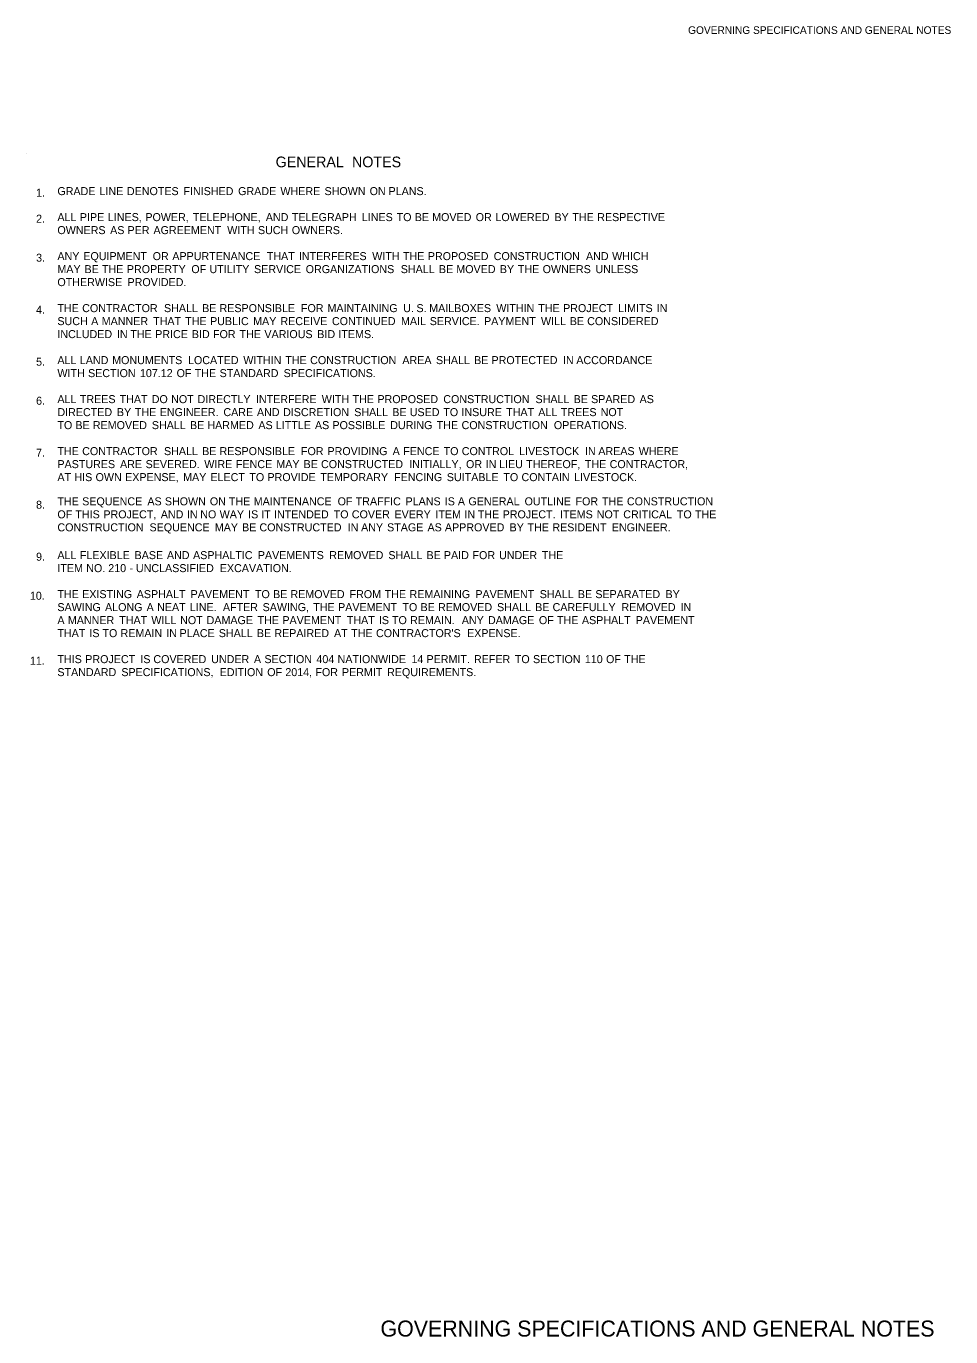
# Model space of a CAD drawing. Extents: x -2857 to 1648, y -1031 to 968.
# Drawn here: x 261 to 1648, y -1031 to 935 of the extents above; entities that cross this region are included whole.
import ezdxf

# ---------------------------------------------------------------- set-up
doc = ezdxf.new("R2010")
doc.units = 0
for name, color, linetype in [('Default', 7, 'Continuous'), ('R_Annotation', 7, 'Continuous'), ('R_Border', 7, 'Continuous')]:
    doc.layers.add(name, color=color, linetype=linetype)

msp = doc.modelspace()

# ---------------------------------------------------------------- linework, layer by layer
at = {"layer": 'Default'}
msp.add_line((261, 744.8), (261, 744.8), dxfattribs=at)

# ---------------------------------------------------------------- texts
for s, height, p in [('GENERAL', 16, (635.1, 723.6)), (' NOTES', 16, (743.7, 723.6)), ('1.', 12, (275.8, 679.4)), ('GRADE', 12, (307.8, 681.8)), (' LINE', 12, (366.5, 681.8)), (' DENOTES', 12, (407.6, 681.8)), (' FINISHED', 12, (492.4, 681.8)), (' GRADE', 12, (574.4, 681.8)), (' WHERE', 12, (637.8, 681.8)), (' SHOWN', 12, (704, 681.8)), (' ON', 12, (771.6, 681.8)), (' PLANS.', 12, (800, 681.8)), ('2.', 12, (275.8, 640.4)), ('ALL', 12, (307.8, 642.8)), (' PIPE', 12, (337, 642.8)), (' LINES,', 12, (379, 642.8)), (' POWER,', 12, (435.3, 642.8)), (' TELEPHONE,', 12, (506.5, 642.8)), (' AND', 12, (615.9, 642.8)), (' TELEGRAPH', 12, (655, 642.8)), (' LINES', 12, (759.9, 642.8)), (' TO', 12, (812.1, 642.8)), (' BE', 12, (839.3, 642.8)), (' MOVED', 12, (865.4, 642.8)), (' OR', 12, (930.7, 642.8)), (' LOWERED', 12, (960.3, 642.8)), (' BY', 12, (1048.8, 642.8)), (' THE', 12, (1075.7, 642.8)), (' RESPECTIVE', 12, (1113, 642.8)), ('OWNERS', 12, (307.8, 623.3)), (' AS', 12, (382.4, 623.3)), (' PER', 12, (408.5, 623.3)), (' AGREEMENT', 12, (447.4, 623.3)), (' WITH', 12, (558, 623.3)), (' SUCH', 12, (604.1, 623.3)), (' OWNERS.', 12, (654.9, 623.3)), ('3.', 12, (275.8, 581.9)), ('ANY', 12, (307.8, 584.3)), (' EQUIPMENT', 12, (342.2, 584.3)), (' OR', 12, (446.2, 584.3)), (' APPURTENANCE', 12, (475.7, 584.3)), (' THAT', 12, (617.4, 584.3)), (' INTERFERES', 12, (665.5, 584.3)), (' WITH', 12, (775.5, 584.3)), (' THE', 12, (821.6, 584.3)), (' PROPOSED', 12, (858.9, 584.3)), (' CONSTRUCTION', 12, (957.7, 584.3)), (' AND', 12, (1096.1, 584.3)), (' WHICH', 12, (1135.3, 584.3)), ('MAY', 12, (307.8, 564.8)), (' BE', 12, (344, 564.8)), (' THE', 12, (370.2, 564.8)), (' PROPERTY', 12, (407.5, 564.8)), (' OF', 12, (504.2, 564.8)), (' UTILITY', 12, (531.4, 564.8)), (' SERVICE', 12, (598.3, 564.8)), (' ORGANIZATIONS', 12, (675.7, 564.8)), (' SHALL', 12, (818.3, 564.8)), (' BE', 12, (875.5, 564.8)), (' MOVED', 12, (901.6, 564.8)), (' BY', 12, (966.9, 564.8)), (' THE', 12, (993.8, 564.8)), (' OWNERS', 12, (1031.1, 564.8)), (' UNLESS', 12, (1110.3, 564.8)), ('OTHERWISE', 12, (307.8, 545.3)), (' PROVIDED.', 12, (408.5, 545.3)), ('4.', 12, (275.8, 503.9)), ('THE', 12, (307.8, 506.3)), (' CONTRACTOR', 12, (340.5, 506.3)), (' SHALL', 12, (463.2, 506.3)), (' BE', 12, (520.4, 506.3)), (' RESPONSIBLE', 12, (546.5, 506.3)), (' FOR', 12, (668.6, 506.3)), (' MAINTAINING', 12, (708.4, 506.3)), (' U.', 12, (822, 506.3)), (' S.', 12, (841.9, 506.3)), (' MAILBOXES', 12, (861, 506.3)), (' WITHIN', 12, (961.6, 506.3)), (' THE', 12, (1024.5, 506.3)), (' PROJECT', 12, (1061.8, 506.3)), (' LIMITS', 12, (1144.4, 506.3)), (' IN', 12, (1202.2, 506.3)), ('SUCH', 12, (307.8, 486.8)), (' A', 12, (354, 486.8)), (' MANNER', 12, (369.8, 486.8)), (' THAT', 12, (446.9, 486.8)), (' THE', 12, (495, 486.8)), (' PUBLIC', 12, (532.3, 486.8)), (' MAY', 12, (596.9, 486.8)), (' RECEIVE', 12, (637.8, 486.8)), (' CONTINUED', 12, (715.1, 486.8)), (' MAIL', 12, (818.6, 486.8)), (' SERVICE.', 12, (861.8, 486.8)), (' PAYMENT', 12, (943.2, 486.8)), (' WILL', 12, (1028.6, 486.8)), (' BE', 12, (1071.8, 486.8)), (' CONSIDERED', 12, (1097.9, 486.8)), ('INCLUDED', 12, (307.8, 467.3)), (' IN', 12, (392.6, 467.3)), (' THE', 12, (412.7, 467.3)), (' PRICE', 12, (450, 467.3)), (' BID', 12, (505, 467.3)), (' FOR', 12, (536.7, 467.3)), (' THE', 12, (576.5, 467.3)), (' VARIOUS', 12, (613.8, 467.3)), (' BID', 12, (693.1, 467.3)), (' ITEMS.', 12, (724.8, 467.3)), ('5.', 12, (275.8, 425.9)), ('ALL', 12, (307.8, 428.3)), (' LAND', 12, (337, 428.3)), (' MONUMENTS', 12, (385.5, 428.3)), (' LOCATED', 12, (499.2, 428.3)), (' WITHIN', 12, (582.2, 428.3)), (' THE', 12, (645.1, 428.3)), (' CONSTRUCTION', 12, (682.4, 428.3)), (' AREA', 12, (820.7, 428.3)), (' SHALL', 12, (871.1, 428.3)), (' BE', 12, (928.3, 428.3)), (' PROTECTED', 12, (954.4, 428.3)), (' IN', 12, (1061.6, 428.3)), (' ACCORDANCE', 12, (1081.6, 428.3)), ('WITH', 12, (307.8, 408.8)), (' SECTION', 12, (349.3, 408.8)), (' 107.12', 12, (427.1, 408.8)), (' OF', 12, (482.1, 408.8)), (' THE', 12, (509.3, 408.8)), (' STANDARD', 12, (546.6, 408.8)), (' SPECIFICATIONS.', 12, (642.6, 408.8)), ('6.', 12, (275.8, 367.4)), ('ALL', 12, (307.8, 369.8)), (' TREES', 12, (337, 369.8)), (' THAT', 12, (396.7, 369.8)), (' DO', 12, (444.8, 369.8)), (' NOT', 12, (473.9, 369.8)), (' DIRECTLY', 12, (513.6, 369.8)), (' INTERFERE', 12, (601.1, 369.8)), (' WITH', 12, (699.8, 369.8)), (' THE', 12, (746, 369.8)), (' PROPOSED', 12, (783.3, 369.8)), (' CONSTRUCTION', 12, (882.1, 369.8)), (' SHALL', 12, (1020.4, 369.8)), (' BE', 12, (1077.6, 369.8)), (' SPARED', 12, (1103.8, 369.8)), (' AS', 12, (1176.5, 369.8)), ('DIRECTED', 12, (307.8, 350.3)), (' BY', 12, (392.6, 350.3)), (' THE', 12, (419.5, 350.3)), (' ENGINEER.', 12, (456.8, 350.3)), (' CARE', 12, (552.3, 350.3)), (' AND', 12, (602.6, 350.3)), (' DISCRETION', 12, (641.8, 350.3)), (' SHALL', 12, (748.5, 350.3)), (' BE', 12, (805.6, 350.3)), (' USED', 12, (831.8, 350.3)), (' TO', 12, (882.1, 350.3)), (' INSURE', 12, (909.3, 350.3)), (' THAT', 12, (976.4, 350.3)), (' ALL', 12, (1024.5, 350.3)), (' TREES', 12, (1058.4, 350.3)), (' NOT', 12, (1118.1, 350.3)), ('TO', 12, (307.8, 330.8)), (' BE', 12, (330.3, 330.8)), (' REMOVED', 12, (356.5, 330.8)), (' SHALL', 12, (445, 330.8)), (' BE', 12, (502.2, 330.8)), (' HARMED', 12, (528.3, 330.8)), (' AS', 12, (604.8, 330.8)), (' LITTLE', 12, (630.9, 330.8)), (' AS', 12, (689.6, 330.8)), (' POSSIBLE', 12, (715.8, 330.8)), (' DURING', 12, (802.5, 330.8)), (' THE', 12, (872.2, 330.8)), (' CONSTRUCTION', 12, (909.5, 330.8)), (' OPERATIONS.', 12, (1047.9, 330.8)), ('7.', 12, (275.8, 289.4)), ('THE', 12, (307.8, 291.8)), (' CONTRACTOR', 12, (340.5, 291.8)), (' SHALL', 12, (463.2, 291.8)), (' BE', 12, (520.4, 291.8)), (' RESPONSIBLE', 12, (546.5, 291.8)), (' FOR', 12, (668.6, 291.8)), (' PROVIDING', 12, (708.4, 291.8)), (' A', 12, (806.1, 291.8)), (' FENCE', 12, (822, 291.8)), (' TO', 12, (882.6, 291.8)), (' CONTROL', 12, (909.8, 291.8)), (' LIVESTOCK', 12, (995.8, 291.8)), (' IN', 12, (1094.6, 291.8)), (' AREAS', 12, (1114.6, 291.8)), (' WHERE', 12, (1175.2, 291.8)), ('PASTURES', 12, (307.8, 272.3)), (' ARE', 12, (397.3, 272.3)), (' SEVERED.', 12, (435.6, 272.3)), (' WIRE', 12, (523.6, 272.3)), (' FENCE', 12, (571.1, 272.3)), (' MAY', 12, (631.7, 272.3)), (' BE', 12, (672.6, 272.3)), (' CONSTRUCTED', 12, (698.7, 272.3)), (' INITIALLY,', 12, (831, 272.3)), (' OR', 12, (916.2, 272.3)), (' IN', 12, (945.7, 272.3)), (' LIEU', 12, (965.8, 272.3)), (' THEREOF,', 12, (1006.4, 272.3)), (' THE', 12, (1094.3, 272.3)), (' CONTRACTOR,', 12, (1131.6, 272.3)), ('AT', 12, (307.8, 252.8)), (' HIS', 12, (328.9, 252.8)), (' OWN', 12, (360.6, 252.8)), (' EXPENSE,', 12, (404.9, 252.8)), (' MAY', 12, (491.9, 252.8)), (' ELECT', 12, (532.8, 252.8)), (' TO', 12, (591.2, 252.8)), (' PROVIDE', 12, (618.4, 252.8)), (' TEMPORARY', 12, (697.6, 252.8)), (' FENCING', 12, (808.3, 252.8)), (' SUITABLE', 12, (887.4, 252.8)), (' TO', 12, (972.2, 252.8)), (' CONTAIN', 12, (999.4, 252.8)), (' LIVESTOCK.', 12, (1078.2, 252.8)), ('8.', 12, (275.8, 211.4)), ('THE', 12, (307.8, 216.5)), (' SEQUENCE', 12, (340.5, 216.5)), (' AS', 12, (438.3, 216.5)), (' SHOWN', 12, (464.5, 216.5)), (' ON', 12, (532, 216.5)), (' THE', 12, (560.5, 216.5)), (' MAINTENANCE', 12, (597.8, 216.5)), (' OF', 12, (723.6, 216.5)), (' TRAFFIC', 12, (750.7, 216.5)), (' PLANS', 12, (825.5, 216.5)), (' IS', 12, (884.3, 216.5)), (' A', 12, (903.9, 216.5)), (' GENERAL', 12, (919.8, 216.5)), (' OUTLINE', 12, (1004, 216.5)), (' FOR', 12, (1080.4, 216.5)), (' THE', 12, (1120.2, 216.5)), (' CONSTRUCTION', 12, (1157.5, 216.5)), ('OF', 12, (307.8, 197)), (' THIS', 12, (330.3, 197)), (' PROJECT,', 12, (372.3, 197)), (' AND', 12, (458.4, 197)), (' IN', 12, (497.6, 197)), (' NO', 12, (517.6, 197)), (' WAY', 12, (546.7, 197)), (' IS', 12, (589.4, 197)), (' IT', 12, (609, 197)), (' INTENDED', 12, (628.2, 197)), (' TO', 12, (717.7, 197)), (' COVER', 12, (744.9, 197)), (' EVERY', 12, (808.9, 197)), (' ITEM', 12, (870.3, 197)), (' IN', 12, (913.8, 197)), (' THE', 12, (933.8, 197)), (' PROJECT.', 12, (971.1, 197)), (' ITEMS', 12, (1057.2, 197)), (' NOT', 12, (1112.2, 197)), (' CRITICAL', 12, (1152, 197)), (' TO', 12, (1232.4, 197)), (' THE', 12, (1259.6, 197)), ('CONSTRUCTION', 12, (307.8, 177.5)), (' SEQUENCE', 12, (441.5, 177.5)), (' MAY', 12, (539.4, 177.5)), (' BE', 12, (580.3, 177.5)), (' CONSTRUCTED', 12, (606.4, 177.5)), (' IN', 12, (738.7, 177.5)), (' ANY', 12, (758.8, 177.5)), (' STAGE', 12, (797.8, 177.5)), (' AS', 12, (858.4, 177.5)), (' APPROVED', 12, (884.5, 177.5)), (' BY', 12, (981.5, 177.5)), (' THE', 12, (1008.4, 177.5)), (' RESIDENT', 12, (1045.7, 177.5)), (' ENGINEER.', 12, (1134.8, 177.5)), ('9.', 12, (275.8, 133.4)), ('ALL', 12, (307.8, 135.8)), (' FLEXIBLE', 12, (337, 135.8)), (' BASE', 12, (419.1, 135.8)), (' AND', 12, (467.6, 135.8)), (' ASPHALTIC', 12, (506.8, 135.8)), (' PAVEMENTS', 12, (603.9, 135.8)), (' REMOVED', 12, (711.1, 135.8)), (' SHALL', 12, (799.7, 135.8)), (' BE', 12, (856.9, 135.8)), (' PAID', 12, (883, 135.8)), (' FOR', 12, (925.9, 135.8)), (' UNDER', 12, (965.7, 135.8)), (' THE', 12, (1029.8, 135.8)), ('ITEM', 12, (307.8, 116.3)), (' NO.', 12, (346.6, 116.3)), (' 210', 12, (379.6, 116.3)), (' -', 12, (411.4, 116.3)), (' UNCLASSIFIED', 12, (421.1, 116.3)), (' EXCAVATION.', 12, (546.9, 116.3)), ('10.', 12, (266.5, 74.9)), ('THE', 12, (307.8, 77.3)), (' EXISTING', 12, (340.5, 77.3)), (' ASPHALT', 12, (422.3, 77.3)), (' PAVEMENT', 12, (503.1, 77.3)), (' TO', 12, (599.6, 77.3)), (' BE', 12, (626.8, 77.3)), (' REMOVED', 12, (652.9, 77.3)), (' FROM', 12, (741.5, 77.3)), (' THE', 12, (794.2, 77.3)), (' REMAINING', 12, (831.5, 77.3)), (' PAVEMENT', 12, (930.2, 77.3)), (' SHALL', 12, (1026.7, 77.3)), (' BE', 12, (1083.9, 77.3)), (' SEPARATED', 12, (1110.1, 77.3)), (' BY', 12, (1215.4, 77.3)), ('SAWING', 12, (307.8, 57.8)), (' ALONG', 12, (374.8, 57.8)), (' A', 12, (437.1, 57.8)), (' NEAT', 12, (452.9, 57.8)), (' LINE.', 12, (502, 57.8)), ('  AFTER', 12, (547.1, 57.8)), (' SAWING,', 12, (611.1, 57.8)), (' THE', 12, (687, 57.8)), (' PAVEMENT', 12, (724.3, 57.8)), (' TO', 12, (820.8, 57.8)), (' BE', 12, (848, 57.8)), (' REMOVED', 12, (874.2, 57.8)), (' SHALL', 12, (962.7, 57.8)), (' BE', 12, (1019.9, 57.8)), (' CAREFULLY', 12, (1046, 57.8)), (' REMOVED', 12, (1149.3, 57.8)), (' IN', 12, (1237.9, 57.8)), ('A', 12, (307.8, 38.3)), (' MANNER', 12, (319, 38.3)), (' THAT', 12, (396.1, 38.3)), (' WILL', 12, (444.2, 38.3)), (' NOT', 12, (487.4, 38.3)), (' DAMAGE', 12, (527.1, 38.3)), (' THE', 12, (603.5, 38.3)), (' PAVEMENT', 12, (640.8, 38.3)), (' THAT', 12, (737.4, 38.3)), (' IS', 12, (785.5, 38.3)), (' TO', 12, (805.1, 38.3)), (' REMAIN.', 12, (832.3, 38.3)), ('  ANY', 12, (905.4, 38.3)), (' DAMAGE', 12, (949.1, 38.3)), (' OF', 12, (1025.5, 38.3)), (' THE', 12, (1052.7, 38.3)), (' ASPHALT', 12, (1090, 38.3)), (' PAVEMENT', 12, (1170.7, 38.3)), ('THAT', 12, (307.8, 18.8)), (' IS', 12, (351.3, 18.8)), (' TO', 12, (370.9, 18.8)), (' REMAIN', 12, (398.1, 18.8)), (' IN', 12, (466.6, 18.8)), (' PLACE', 12, (486.6, 18.8)), (' SHALL', 12, (545.4, 18.8)), (' BE', 12, (602.5, 18.8)), (' REPAIRED', 12, (628.7, 18.8)), (' AT', 12, (718.2, 18.8)), (' THE', 12, (743.9, 18.8)), (" CONTRACTOR'S", 12, (781.2, 18.8)), (' EXPENSE.', 12, (917.7, 18.8)), ('11.', 12, (266.5, -22.6)), ('THIS', 12, (307.8, -20.2)), (' PROJECT', 12, (345.1, -20.2)), (' IS', 12, (427.7, -20.2)), (' COVERED', 12, (447.3, -20.2)), (' UNDER', 12, (534, -20.2)), (' A', 12, (598.1, -20.2)), (' SECTION', 12, (613.9, -20.2)), (' 404', 12, (691.8, -20.2)), (' NATIONWIDE', 12, (723.6, -20.2)), (' 14', 12, (834.4, -20.2)), (' PERMIT.', 12, (856.9, -20.2)), (' REFER', 12, (928.1, -20.2)), (' TO', 12, (989.4, -20.2)), (' SECTION', 12, (1016.6, -20.2)), (' 110', 12, (1094.4, -20.2)), (' OF', 12, (1126.2, -20.2)), (' THE', 12, (1153.4, -20.2)), ('STANDARD', 12, (307.8, -39.7)), (' SPECIFICATIONS,', 12, (399.2, -39.7)), (' EDITION', 12, (546.7, -39.7)), (' OF', 12, (618, -39.7)), (' 2014,', 12, (645.2, -39.7)), (' FOR', 12, (690.3, -39.7)), (' PERMIT', 12, (730.1, -39.7)), (' REQUIREMENTS.', 12, (797.8, -39.7))]:
    msp.add_text(s, height=height, dxfattribs=at).set_placement(p)
at = {"layer": 'R_Annotation'}
msp.add_text('GOVERNING SPECIFICATIONS AND GENERAL NOTES', height=24, dxfattribs=at).set_placement((792.3, -1030.3))
at = {"layer": 'R_Border'}
msp.add_text('GOVERNING SPECIFICATIONS AND GENERAL NOTES', height=11.4, dxfattribs=at).set_placement((1253.7, 923.6))

doc.saveas('drawing.dxf')
